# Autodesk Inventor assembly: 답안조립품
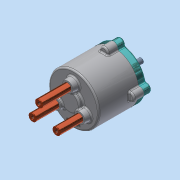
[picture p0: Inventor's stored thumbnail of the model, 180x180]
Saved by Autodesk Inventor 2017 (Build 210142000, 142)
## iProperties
Part Number: 답안조립품
Material: 일반
Document SubType Name: Assembly
Designer: MRC
Mass: 1236.64 g
Surface Area: 1770.13 cm^2
Volume: 433.791 cm^3
Density: 2.85078 g/cm^3
Author: MRC
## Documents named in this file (14)
- C:\Users\MRC\Desktop\610708V1012\답안조립품.iam
- C:\Users\MRC\Desktop\610708V1012\본체.ipt
- C:\Users\MRC\Desktop\610708V1012\가변스프링-01.ipt
- C:\Users\MRC\Desktop\610708V1012\가변스프링-02.ipt
- C:\Users\MRC\Desktop\610708V1012\가변스프링-03.ipt
- C:\Users\MRC\Desktop\610708V1012\멈춤링 10 x 1.ipt
- C:\Users\MRC\Desktop\610708V1012\멈춤링 22 x 1.2.ipt
- C:\Users\MRC\Desktop\610708V1012\메인 축.ipt
- C:\Users\MRC\Desktop\610708V1012\베어링 NA 4900.ipt
- C:\Users\MRC\Desktop\610708V1012\볼트 M5.ipt
- C:\Users\MRC\Desktop\610708V1012\슬라이드 축.ipt
- C:\Users\MRC\Desktop\610708V1012\오일실.ipt
- C:\Users\MRC\Desktop\610708V1012\커버.ipt
- C:\Users\MRC\Desktop\610708V1012\판캠.ipt
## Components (3 placed, 3 different names)
1. 가변스프링-01:1
2. 가변스프링-02:1
3. 가변스프링-03:1
